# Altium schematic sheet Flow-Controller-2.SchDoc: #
size A3; ApprovedBy: #; DrawnBy: #; DocumentNumber: #; Revision: #; SheetNumber: 2; SheetTotal: 2; DocumentRevision: #; Reviewed: #; QA: #; CM: #; ECR: #; PageSetup: Record=PageOptions¦CenterHorizontal=True¦CenterVertical=True¦PrintScale=0.97¦XCorrection=1.00¦YCorrection=1.00¦PrintKind=1¦BorderSize=5000000¦LeftOffset=0¦BottomOffset=0¦Orientation=2¦PaperLength=1000¦PaperWidth=1000¦Scale=100¦PaperSource=7¦PrintQuality=-4¦MediaType=1¦DitherType=10¦PaperKind=A3¦PrintScaleMode=1
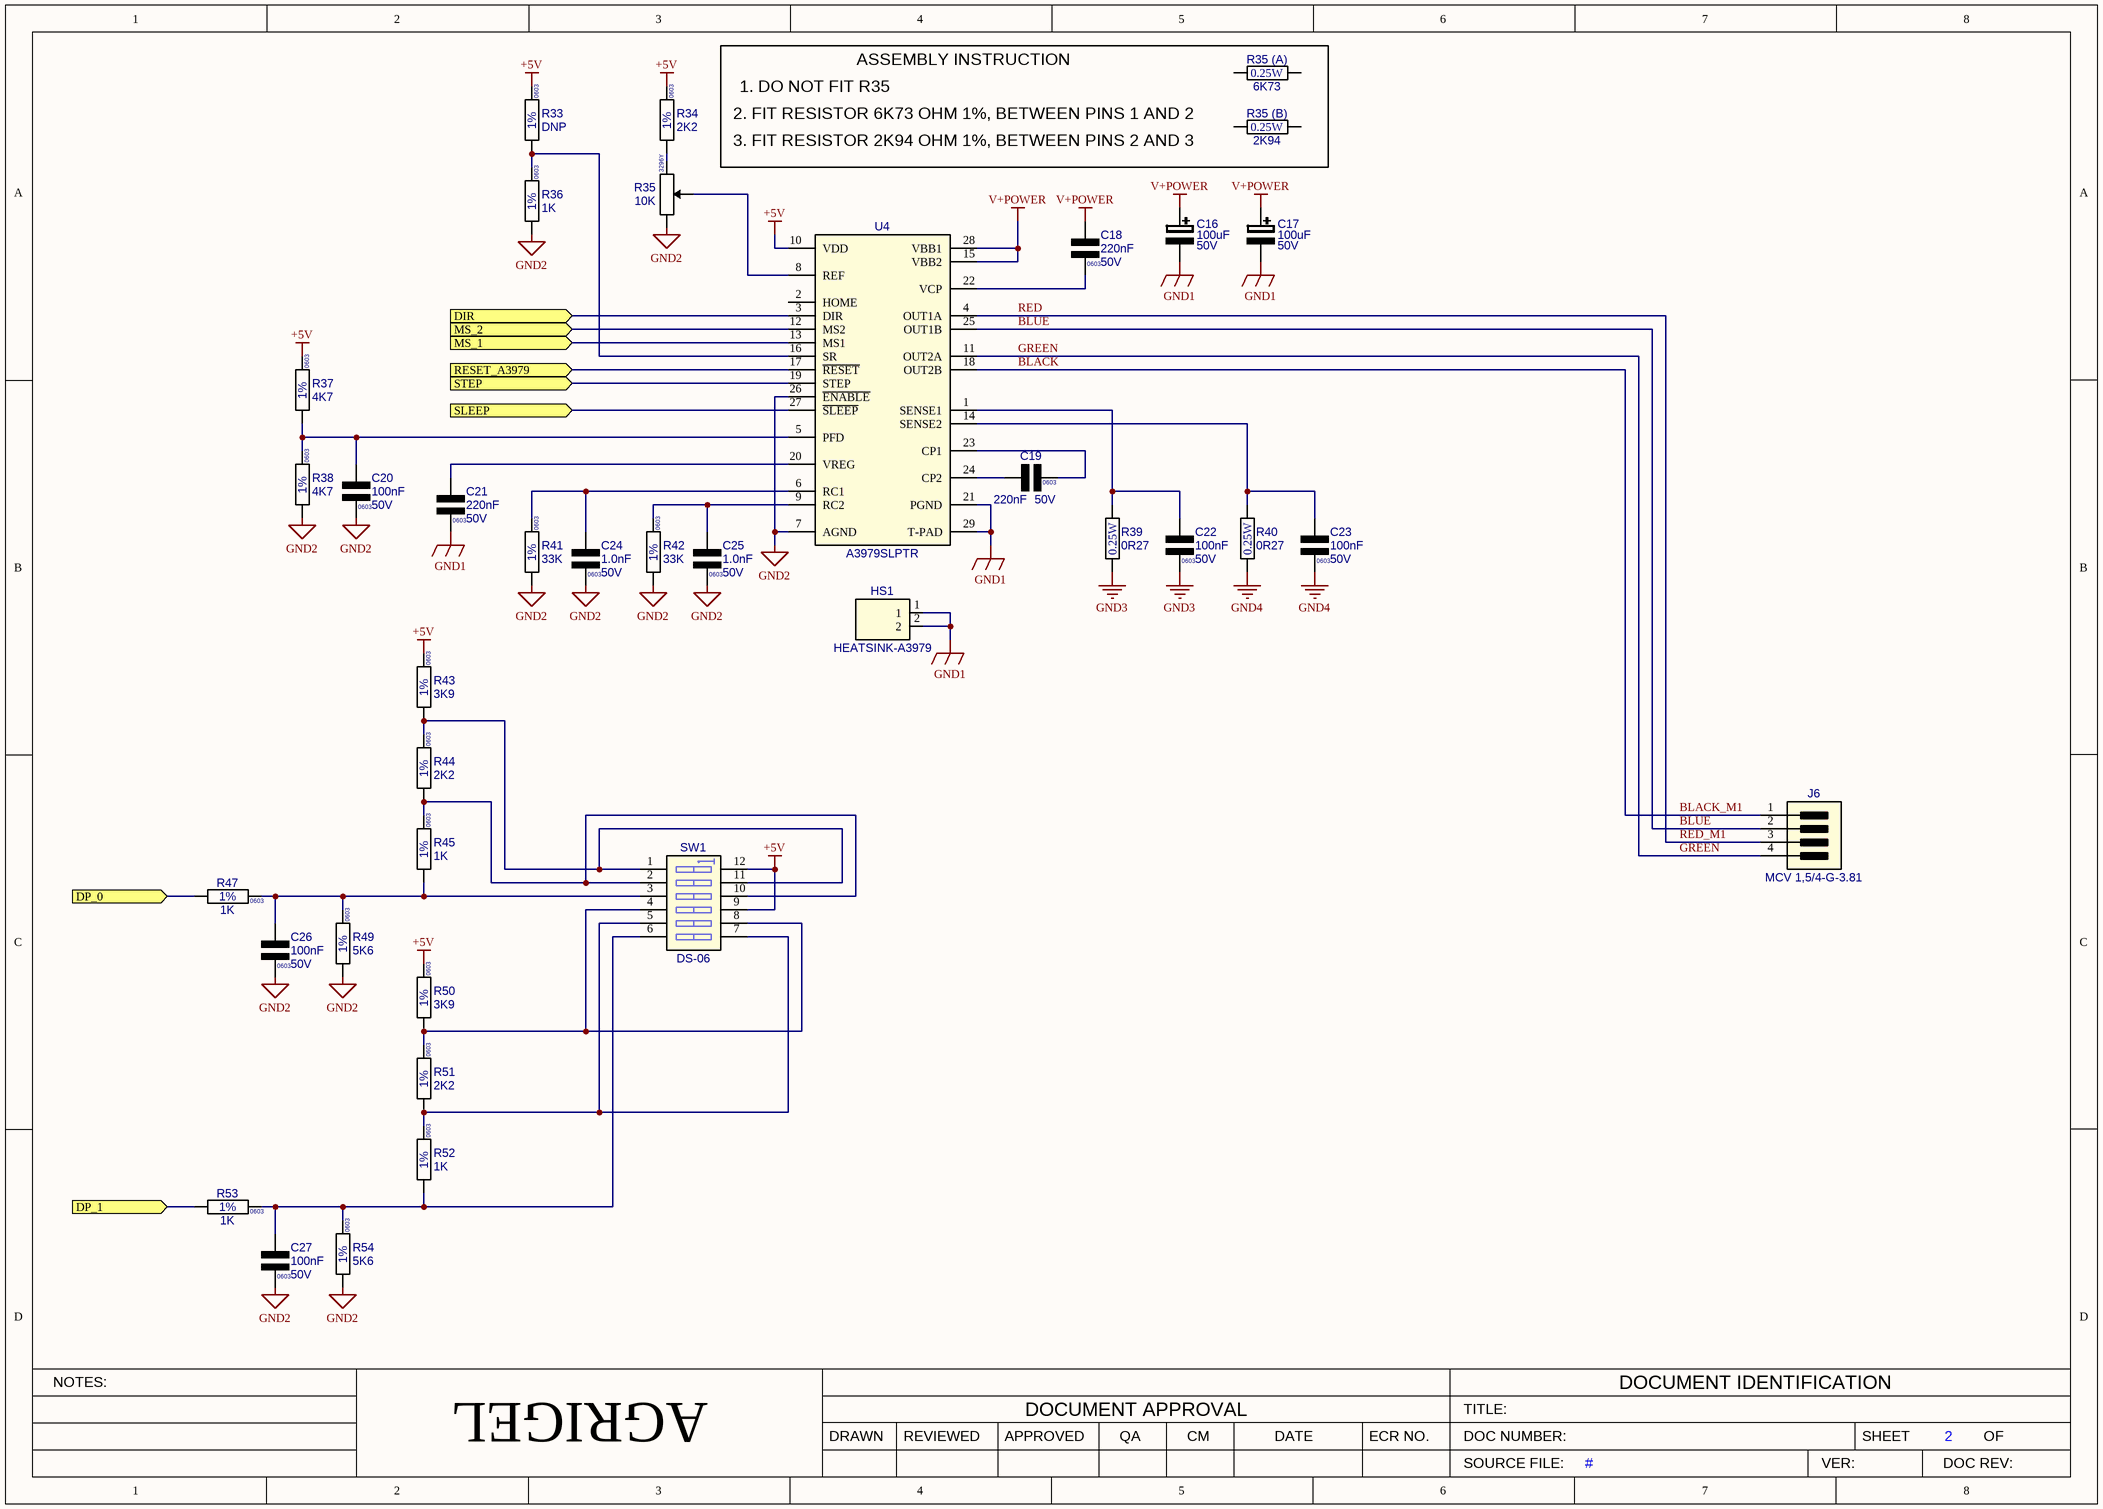
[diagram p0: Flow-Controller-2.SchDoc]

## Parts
C16  value 100uF  Voltage: 50V  [CAP-EL-SMD-8x10.5]  (hidden comment: 100uF-50V-20%-LZ)
C17  value 100uF  Voltage: 50V  [CAP-EL-SMD-8x10.5]  (hidden comment: 100uF-50V-20%-LZ)
C18  value 220nF  Voltage: 50V  Text1: 0603  [CAPC0603X85N]  (hidden comment: 220nF_C0603_50V_10%_X7R)
C19  value 220nF  Voltage: 50V  Text1: 0603  [CAPC0603X85N]  (hidden comment: 220nF_C0603_50V_10%_X7R)
C20  value 100nF  Voltage: 50V  Text1: 0603  [CAPC0603X85N]  (hidden comment: 100nF_C0603_50V_10%_X7R)
C21  value 220nF  Voltage: 50V  Text1: 0603  [CAPC0603X85N]  (hidden comment: 220nF_C0603_50V_10%_X7R)
C22  value 100nF  Voltage: 50V  Text1: 0603  [CAPC0603X85N]  (hidden comment: 100nF_C0603_50V_10%_X7R)
C23  value 100nF  Voltage: 50V  Text1: 0603  [CAPC0603X85N]  (hidden comment: 100nF_C0603_50V_10%_X7R)
C24  value 1.0nF  Voltage: 50V  Text1: 0603  [CAPC0603X85N]  (hidden comment: 1.0nF_C0603_50V_10%_X7R)
C25  value 1.0nF  Voltage: 50V  Text1: 0603  [CAPC0603X85N]  (hidden comment: 1.0nF_C0603_50V_10%_X7R)
C26  value 100nF  Voltage: 50V  Text1: 0603  [CAPC0603X85N]  (hidden comment: 100nF_C0603_50V_10%_X7R)
C27  value 100nF  Voltage: 50V  Text1: 0603  [CAPC0603X85N]  (hidden comment: 100nF_C0603_50V_10%_X7R)
HS1  Heatsink-A3979  [HEATSINK-A3979]
J6  MCV 1,5/4-G-3.81  [ECH381V-04P]
R33  value DNP  Tol: 1%  Text1: 0603  [RESC0603X60N]  (hidden comment: DNP_R0603_1%)
R34  value 2K2  Tol: 1%  Text1: 0603  [RESC0603X60N]  (hidden comment: 2K2_R0603_1%)
R35  value 10K  Text1: 3296Y  [3296Y-THP]  (hidden comment: 3296Y-1-103)
R35_(A)  value 6K73  Watt: 0.25W  [RES-0.250W]  (hidden comment: 6K73-0.250W-1%_H)
R35_(B)  value 2K94  Watt: 0.25W  [RES-0.250W]  (hidden comment: 2K94-0.250W-1%_H)
R36  value 1K  Tol: 1%  Text1: 0603  [RESC0603X60N]  (hidden comment: 1K_R0603_1%)
R37  value 4K7  Tol: 1%  Text1: 0603  [RESC0603X60N]  (hidden comment: 4K7_R0603_1%)
R38  value 4K7  Tol: 1%  Text1: 0603  [RESC0603X60N]  (hidden comment: 4K7_R0603_1%)
R39  value 0R27  Watt: 0.25W  [RES-0.250W]  (hidden comment: 0R27-0.250W-5%)
R40  value 0R27  Watt: 0.25W  [RES-0.250W]  (hidden comment: 0R27-0.250W-5%)
R41  value 33K  Tol: 1%  Text1: 0603  [RESC0603X60N]  (hidden comment: 33K_R0603_1%)
R42  value 33K  Tol: 1%  Text1: 0603  [RESC0603X60N]  (hidden comment: 33K_R0603_1%)
R43  value 3K9  Tol: 1%  Text1: 0603  [RESC0603X60N]  (hidden comment: 3K9_R0603_1%)
R44  value 2K2  Tol: 1%  Text1: 0603  [RESC0603X60N]  (hidden comment: 2K2_R0603_1%)
R45  value 1K  Tol: 1%  Text1: 0603  [RESC0603X60N]  (hidden comment: 1K_R0603_1%)
R47  value 1K  Tol: 1%  Text1: 0603  [RESC0603X60N]  (hidden comment: 1K_R0603_1%)
R49  value 5K6  Tol: 1%  Text1: 0603  [RESC0603X60N]  (hidden comment: 5K6_R0603_1%)
R50  value 3K9  Tol: 1%  Text1: 0603  [RESC0603X60N]  (hidden comment: 3K9_R0603_1%)
R51  value 2K2  Tol: 1%  Text1: 0603  [RESC0603X60N]  (hidden comment: 2K2_R0603_1%)
R52  value 1K  Tol: 1%  Text1: 0603  [RESC0603X60N]  (hidden comment: 1K_R0603_1%)
R53  value 1K  Tol: 1%  Text1: 0603  [RESC0603X60N]  (hidden comment: 1K_R0603_1%)
R54  value 5K6  Tol: 1%  Text1: 0603  [RESC0603X60N]  (hidden comment: 5K6_R0603_1%)
SW1  DS-06  [DIP-SW6]
U4  A3979SLPTR  [TSSOP28-4.4-LP]

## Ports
DIR, DP_0, DP_1, MS_1, MS_2, RESET_A3979, SLEEP, STEP

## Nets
+5V: R33.1 R34.1 R37.1 R43.1 R50.1 SW1.9(B4) SW1.12(B1) U4.10(VDD)
GND1: C16.2 C17.2 C21.2 HS1.1 HS1.2 U4.21(PGND) U4.29(T-PAD)
GND2: C20.2 C24.2 C25.2 C26.2 C27.2 R35.3 R36.2 R38.2 R41.2 R42.2 R49.2 R54.2 U4.7(AGND) U4.26(~{ENABLE})
GND3: C22.2 R39.1
GND4: C23.2 R40.1
V+POWER: C16.1 C17.1 C18.1 U4.15(VBB2) U4.28(VBB1)
BLACK: J6.1 U4.18(OUT2B)  [also labelled BLACK_M1]
BLUE: J6.2 U4.25(OUT1B)
DIR: U4.3(DIR) ; port DIR
DP_0: R47.1 ; port DP_0
DP_1: R53.1 ; port DP_1
GREEN: J6.4 U4.11(OUT2A)
MS_1: U4.13(MS1) ; port MS_1
MS_2: U4.12(MS2) ; port MS_2
RED: J6.3 U4.4(OUT1A)  [also labelled RED_M1]
RESET_A3979: U4.17(~{RESET}) ; port RESET_A3979
SLEEP: U4.27(~{SLEEP}) ; port SLEEP
STEP: U4.19(STEP) ; port STEP
NetC18_2: C18.2 U4.22(VCP)
NetC19_1: C19.1 U4.24(CP2)
NetC19_2: C19.2 U4.23(CP1)
NetC20_1: C20.1 R37.2 R38.1 U4.5(PFD)
NetC21_1: C21.1 U4.20(VREG)
NetC22_1: C22.1 R39.2 U4.1(SENSE1)
NetC23_1: C23.1 R40.2 U4.14(SENSE2)
NetC24_1: C24.1 R41.1 U4.6(RC1)
NetC25_1: C25.1 R42.1 U4.9(RC2)
NetC26_1: C26.1 R45.2 R47.2 R49.1 SW1.3(A3)
NetC27_1: C27.1 R52.2 R53.2 R54.1 SW1.6(A6)
NetR33_2: R33.2 R36.1 U4.16(SR)
NetR34_2: R34.2 R35.1
NetR35_2: R35.2 U4.8(REF)
NetR43_2: R43.2 R44.1 SW1.1(A1) SW1.11(B2)
NetR44_2: R44.2 R45.1 SW1.2(A2) SW1.10(B3)
NetR50_2: R50.2 R51.1 SW1.4(A4) SW1.8(B5)
NetR51_2: R51.2 R52.1 SW1.5(A5) SW1.7(B6)

Not connected (* = marked no-connect by the designer): R35_(A) 1 2; R35_(B) 1 2; U4 2(HOME)

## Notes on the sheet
- 1. DO NOT FIT R35
- ASSEMBLY INSTRUCTION
- 2. FIT RESISTOR 6K73 OHM 1%, BETWEEN PINS 1 AND 2
- 3. FIT RESISTOR 2K94 OHM 1%, BETWEEN PINS 2 AND 3

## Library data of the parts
C16 C17 = 100uF-50V-20%-LZ_V: Cap Electrolytic SMD Low Imp; Manufacturer: KJ Electronics; Part Number: 50LZ101MLC8×10.5EC; Tol: 20%
C18 C21 = 220nF_0603N_50V_10%_X7R_V: Cap Ceramic X7R; Manufacturer: Various; Part Number: 220nF 0603 50V 10% X7R; Board Tech: SMD; Tol: 10%
C19 = 220nF_0603N_50V_10%_X7R_H: Cap Ceramic X7R; Manufacturer: Various; Part Number: 220nF 0603 50V 10% X7R; Board Tech: SMD; Tol: 10%
C20 C22 C23 C26 C27 = 100nF_0603N_50V_10%_X7R_V: Cap Ceramic X7R; Manufacturer: Various; Part Number: 100nF 0603 50V 10% X7R; Board Tech: SMD; Tol: 10%
C24 C25 = 1nF_0603N_50V_10%_X7R_V: Cap Ceramic X7R; Manufacturer: Various; Part Number: 1.0nF 0603 50V 10% X7R; Board Tech: SMD; Tol: 10%; Reutech PN: 5910-CA-0401
HS1 = Heatsink-A3979: Heatsink Vertical PCB Mount A3979; Manufacturer: Agrigel; Board Tech: THP
J6 = MCV 1,5/4-G-3.81: Header Pluggable 3.81mm Vertical; Manufacturer: Phoenix; Board Tech: THP
R33 = DNP_0603_V: Resistor Chip SMD; Manufacturer: Various; Watt: 100mW
R34 R44 R51 = 2K2_0603_V: Resistor Chip SMD; Manufacturer: Various; Part Number: 2K2 0603 1%; Watt: 100mW; EDM-PN: RES232
R35 = 10K_3296Y-1-103_THP_V: Variable Resistor THP; Manufacturer: BOURNS
R35_(A) = 6K73-0.250W-1%_H: Resistor Metal Film; Manufacturer: Various; Part Number: 6K73 1% 0.25W; Board Tech: THP; Tol: 1%
R35_(B) = 2K94-0.250W-1%_H: Resistor Metal Film; Manufacturer: Various; Part Number: 2K94 1% 0.25W; Board Tech: THP; Tol: 1%
R36 R45 R52 = 1K_0603_V: Resistor Chip SMD; Manufacturer: Various; Part Number: 1K 0603 1%; Watt: 100mW
R37 R38 = 4K7_0603_V: Resistor Chip SMD; Manufacturer: Various; Part Number: 4K7 0603 1%; Watt: 100mW
R39 R40 = 0R27-0.250W-5%_V: Resistor Metal Film; Manufacturer: Various; Part Number: 0R27 5% 0.25W; Board Tech: THP; Tol: 5%
R41 R42 = 33K_0603_V: Resistor Chip SMD; Manufacturer: Various; Part Number: 33K 0603 1%; Watt: 100mW
R43 R50 = 3K9_0603_V: Resistor Chip SMD; Manufacturer: Various; Part Number: 3K9 0603 1%; Watt: 100mW
R47 R53 = 1K_0603_H: Resistor Chip SMD; Manufacturer: Various; Part Number: 1K 0603 1%; Watt: 100mW
R49 R54 = 5K6_0603_V: Resistor Chip SMD; Manufacturer: Various; Part Number: 5K6 0603 1%; Watt: 100mW
SW1 = SW-DIP-DS-06: DIP Slide Switch; Manufacturer: Diptronics; Board Tech: THP
U4 = A3979SLPTR_TSSOP28: IC Microstepping DMOS Driver; Manufacturer: Allegro; Board Tech: SMD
